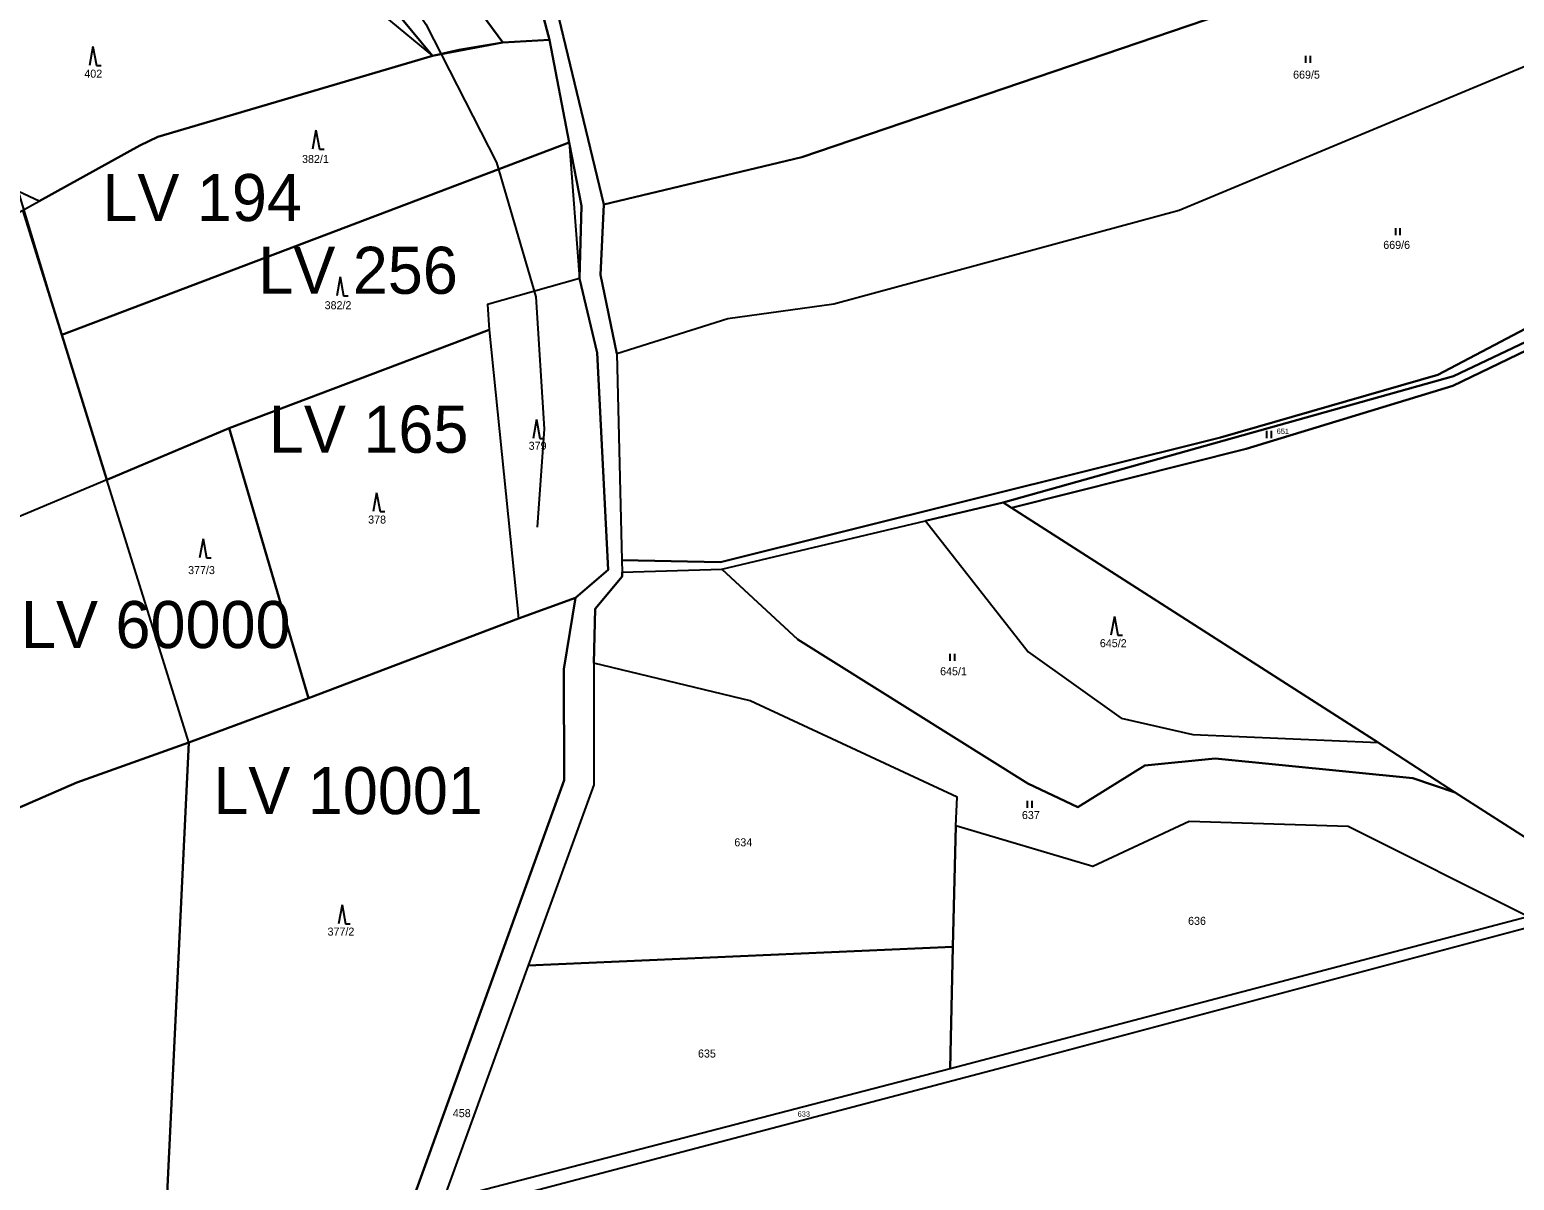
# Model space of a CAD drawing. Extents: x -590606 to -587796, y -1065936 to -1062515.
# Drawn here: x -590130 to -589814.6, y -1065080 to -1064835.5 of the extents above; entities that cross this region are included whole.
import ezdxf

# ---------------------------------------------------------------- set-up
doc = ezdxf.new("R2010")
doc.units = 0
for name, color, linetype in [('Lesy', 7, 'Continuous'), ('Parcela nároku', 7, 'Continuous'), ('Plocha pro ocenění', 7, 'Continuous'), ('Tok', 7, 'Continuous'), ('Vrstva 30', 7, 'Continuous'), ('Čísla LV', 7, 'Continuous')]:
    doc.layers.add(name, color=color, linetype=linetype)

msp = doc.modelspace()

# ---------------------------------------------------------------- linework, layer by layer
at = {"layer": 'Lesy'}
for p, q in [((-590123.19, -1064900.34), (-590015.37, -1064859.51)), ((-590096.21, -1064986.96), (-590070.76, -1064977.54))]:
    msp.add_line(p, q, dxfattribs=at)
for points in [[(-590044.4, -1064841.09), (-590029.51, -1064838.25), (-590019.58, -1064837.67)], [(-590131.43, -1064873.88), (-590127.95, -1064871.98), (-590106.62, -1064860.16), (-590102.75, -1064858.29), (-590044.4, -1064841.09)], [(-590113.59, -1064931.15), (-590087.61, -1064920.23), (-590032.41, -1064899.32)], [(-590087.61, -1064920.23), (-590070.76, -1064977.54), (-590026.19, -1064960.68), (-590014.04, -1064956.28)]]:
    msp.add_lwpolyline(points, dxfattribs=at)
at = {"layer": 'Parcela nároku'}
for points in [[(-590085.05, -1064746.07), (-590075.63, -1064745.31), (-590052.18, -1064731.26), (-590049.73, -1064728.85), (-590029.38, -1064789.34), (-590050.58, -1064809.55), (-590029.51, -1064838.25), (-590038.82, -1064839.84), (-590044.4, -1064841.09), (-590051.27, -1064832.84), (-590064.68, -1064824.28), (-590070.56, -1064805.35), (-590079.14, -1064802.65), (-590083.28, -1064800.94), (-590090.57, -1064795.95)], [(-589879.87, -1064753.99), (-589868.03, -1064748.13), (-589866.87, -1064751.2), (-589721.04, -1064765.62), (-589732.48, -1064773.33), (-589781.14, -1064797.6), (-589848.05, -1064822.46), (-589965.99, -1064862.62), (-590008.01, -1064872.65), (-590021.45, -1064817.05), (-590021.33, -1064814.7), (-589976.81, -1064797.92), (-589940.65, -1064780.54)], [(-590050.58, -1064809.55), (-590029.38, -1064789.34), (-590030.32, -1064781.93), (-590026.74, -1064766.14), (-590014.61, -1064753.36), (-589996.74, -1064775.17), (-590001.82, -1064781.5), (-590022.96, -1064799.52), (-590024.4, -1064815.82), (-590024.63, -1064818.7), (-590019.58, -1064837.67), (-590029.51, -1064838.25)], [(-589848.05, -1064822.46), (-589781.14, -1064797.6), (-589732.48, -1064773.33), (-589721.04, -1064765.62), (-589713.8, -1064760.35), (-589694.16, -1064785.11), (-589709.51, -1064796.54), (-589749.8, -1064818.94), (-589790.83, -1064834.34), (-589885.81, -1064873.92), (-589959.21, -1064893.84), (-589981.68, -1064896.99), (-590005.25, -1064904.42), (-590008.77, -1064887.64), (-590008.01, -1064872.65), (-589965.99, -1064862.62)], [(-589749.8, -1064818.94), (-589790.83, -1064834.34), (-589885.81, -1064873.92), (-589959.21, -1064893.84), (-589981.68, -1064896.99), (-590005.25, -1064904.42), (-590004.21, -1064948.26), (-589983.27, -1064948.69), (-589877.03, -1064922.22), (-589830.91, -1064908.85), (-589764.34, -1064873.79), (-589722.86, -1064853.73), (-589698.59, -1064837.06), (-589669.05, -1064824.3), (-589664.99, -1064821.89), (-589694.16, -1064785.11), (-589709.51, -1064796.54)], [(-590182.24, -1064846.33), (-590153.03, -1064819.2), (-590124.7, -1064831.07), (-590079.14, -1064802.65), (-590070.56, -1064805.35), (-590064.68, -1064824.28), (-590051.27, -1064832.84), (-590044.4, -1064841.09), (-590102.75, -1064858.29), (-590106.62, -1064860.16), (-590127.95, -1064871.98), (-590132.38, -1064869.89)], [(-589830.91, -1064908.85), (-589877.03, -1064922.22), (-589983.27, -1064948.69), (-590004.21, -1064948.26), (-590004.15, -1064950.82), (-589982.95, -1064950.18), (-589939.73, -1064939.92), (-589923.24, -1064936.02), (-589827.57, -1064909.16), (-589809.38, -1064900.48), (-589740.68, -1064866.6), (-589722.41, -1064857.38), (-589696.42, -1064842.01), (-589688.26, -1064837.19), (-589677.04, -1064831.33), (-589667.75, -1064826.48), (-589669.05, -1064824.3), (-589698.59, -1064837.06), (-589722.86, -1064853.73), (-589764.34, -1064873.79)], [(-590102.75, -1064858.29), (-590044.4, -1064841.09), (-590038.82, -1064839.84), (-590029.51, -1064838.25), (-590019.58, -1064837.67), (-590015.37, -1064859.51), (-590123.19, -1064900.34), (-590131.43, -1064873.88), (-590127.95, -1064871.98), (-590106.62, -1064860.16)], [(-590032.74, -1064893.95), (-590032.41, -1064899.32), (-590087.61, -1064920.23), (-590113.59, -1064931.15), (-590123.19, -1064900.34), (-590015.37, -1064859.51), (-590012.77, -1064872.97), (-590013.23, -1064888.37)], [(-590235.19, -1064919.07), (-590258.37, -1064938.81), (-590256.84, -1064941.98), (-590233.92, -1064922), (-590180.87, -1064901.24), (-590131.43, -1064873.88), (-590127.95, -1064871.98), (-590132.38, -1064869.89), (-590182.23, -1064898.16)], [(-590306.19, -1064982.83), (-590256.84, -1064941.98), (-590233.92, -1064922), (-590180.87, -1064901.24), (-590131.43, -1064873.88), (-590123.19, -1064900.34), (-590113.59, -1064931.15), (-590167.74, -1064953.92), (-590233.72, -1064986.21), (-590284.11, -1065022.42), (-590293.83, -1065027.95)], [(-590013.23, -1064888.37), (-590032.74, -1064893.95), (-590032.41, -1064899.32), (-590026.19, -1064960.68), (-590014.04, -1064956.28), (-590007.09, -1064950.34), (-590009.44, -1064904.18)], [(-590087.61, -1064920.23), (-590032.41, -1064899.32), (-590026.19, -1064960.68), (-590070.76, -1064977.54)], [(-589809.38, -1064900.48), (-589827.57, -1064909.16), (-589923.24, -1064936.02), (-589921.46, -1064937.16), (-589871.6, -1064924.56), (-589827.68, -1064911.18), (-589808.02, -1064901.71)], [(-589718.4, -1064982.65), (-589808.02, -1064901.71), (-589827.68, -1064911.18), (-589871.6, -1064924.56), (-589921.46, -1064937.16), (-589843.52, -1064987), (-589827.23, -1064997.59), (-589795.76, -1065017.7), (-589790.16, -1065012.34), (-589792.56, -1065010.99), (-589738.86, -1064988.82)], [(-590113.59, -1064931.15), (-590087.61, -1064920.23), (-590070.76, -1064977.54), (-590096.21, -1064986.96)], [(-590284.11, -1065022.42), (-590270.57, -1065073.39), (-590227.11, -1065047.54), (-590206.41, -1065035.68), (-590149.81, -1065008.44), (-590119.96, -1064995.5), (-590096.21, -1064986.96), (-590113.59, -1064931.15), (-590167.74, -1064953.92), (-590233.72, -1064986.21)], [(-589843.52, -1064987), (-589921.46, -1064937.16), (-589923.24, -1064936.02), (-589939.73, -1064939.92), (-589917.91, -1064967.76), (-589898.15, -1064981.84), (-589882.91, -1064985.28)], [(-589939.73, -1064939.92), (-589917.91, -1064967.76), (-589898.15, -1064981.84), (-589882.91, -1064985.28), (-589843.52, -1064987), (-589827.23, -1064997.59), (-589836.22, -1064994.59), (-589878.15, -1064990.41), (-589893.12, -1064991.88), (-589907.33, -1065000.76), (-589917.96, -1064995.7), (-589966.86, -1064965.11), (-589982.95, -1064950.18)], [(-589893.12, -1064991.88), (-589878.15, -1064990.41), (-589836.22, -1064994.59), (-589827.23, -1064997.59), (-589795.76, -1065017.7), (-589802.07, -1065023.73), (-589806.02, -1065022.39), (-589811.77, -1065023.97), (-589849.91, -1065004.87), (-589883.73, -1065003.75), (-589904.18, -1065013.33), (-589933.24, -1065004.69), (-589933.01, -1064998.63), (-589976.96, -1064978.12), (-590010.18, -1064970.13), (-590009.89, -1064958.56), (-590004.13, -1064951.75), (-590004.15, -1064950.82), (-589982.95, -1064950.18), (-589966.86, -1064965.11), (-589917.96, -1064995.7), (-589907.33, -1065000.76)], [(-590087.91, -1065095.23), (-590071.31, -1065090.46), (-590048.46, -1065083.71), (-590016.47, -1064995), (-590016.56, -1064971.44), (-590014.04, -1064956.28), (-590026.19, -1064960.68), (-590070.76, -1064977.54), (-590096.21, -1064986.96), (-590100.91, -1065085.81), (-590171.34, -1065136.57), (-590141.63, -1065124.76), (-590094.63, -1065099.49)], [(-589933.01, -1064998.63), (-589976.96, -1064978.12), (-590010.18, -1064970.13), (-590010.19, -1064996.02), (-590024.11, -1065034.41), (-589933.87, -1065030.44), (-589933.24, -1065004.69)], [(-590186.86, -1065144.42), (-590171.34, -1065136.57), (-590100.91, -1065085.81), (-590096.21, -1064986.96), (-590119.96, -1064995.5), (-590149.81, -1065008.44), (-590206.41, -1065035.68), (-590227.11, -1065047.54)], [(-589811.77, -1065023.97), (-589849.91, -1065004.87), (-589883.73, -1065003.75), (-589904.18, -1065013.33), (-589933.24, -1065004.69), (-589933.87, -1065030.44), (-589934.45, -1065056.25)], [(-589806.02, -1065022.39), (-589802.07, -1065023.73), (-589923.15, -1065056.06), (-590043.11, -1065087.66), (-590042.18, -1065084.25), (-589934.45, -1065056.25), (-589811.77, -1065023.97)], [(-589731.97, -1065078.6), (-589747.98, -1065071.62), (-589756.67, -1065059.05), (-589771, -1065049.48), (-589784.67, -1065037.04), (-589802.07, -1065023.73), (-589923.15, -1065056.06), (-590043.11, -1065087.66), (-590064.6, -1065165.95), (-590006.04, -1065151.63), (-589920.53, -1065125.45)], [(-590024.11, -1065034.41), (-590042.18, -1065084.25), (-589934.45, -1065056.25), (-589933.87, -1065030.44)]]:
    msp.add_lwpolyline(points, close=True, dxfattribs=at)
for points in [[(-590021.45, -1064817.05), (-590008.01, -1064872.65), (-590008.77, -1064887.64), (-590005.25, -1064904.42), (-590004.21, -1064948.26), (-590004.15, -1064950.82), (-590004.13, -1064951.75), (-590009.89, -1064958.56), (-590010.18, -1064970.13), (-590010.19, -1064996.02), (-590024.11, -1065034.41), (-590042.18, -1065084.25)], [(-590048.46, -1065083.71), (-590016.47, -1064995), (-590016.56, -1064971.44), (-590014.04, -1064956.28), (-590007.09, -1064950.34), (-590009.44, -1064904.18), (-590013.23, -1064888.37), (-590012.77, -1064872.97), (-590015.37, -1064859.51), (-590019.58, -1064837.67), (-590024.63, -1064818.7)]]:
    msp.add_lwpolyline(points, dxfattribs=at)
at = {"layer": 'Plocha pro ocenění'}
for points in [[(-590162.33, -1064773.04), (-590115.36, -1064781.23), (-590111.01, -1064781.85), (-590090.57, -1064795.95), (-590083.28, -1064800.94), (-590070.56, -1064805.35), (-590064.68, -1064824.28), (-590044.4, -1064841.09), (-590029.51, -1064838.25), (-590019.58, -1064837.67), (-590015.37, -1064859.51), (-590013.23, -1064888.37), (-590009.44, -1064904.18), (-590007.09, -1064950.34), (-590014.04, -1064956.28), (-590016.56, -1064971.44), (-590016.47, -1064995), (-590048.46, -1065083.71)], [(-590171.34, -1065136.57), (-590100.91, -1065085.81), (-590096.21, -1064986.96), (-590113.59, -1064931.15), (-590123.19, -1064900.34), (-590132.38, -1064869.89), (-590182.24, -1064846.33), (-590220.42, -1064866.89), (-590318.99, -1064904.37), (-590325.07, -1064907.04), (-590326.4, -1064871.7), (-590357.08, -1064885.44), (-590371.89, -1064892.14), (-590406.17, -1064909.87), (-590416.8, -1064913.27), (-590479.54, -1064933.75)]]:
    msp.add_lwpolyline(points, dxfattribs=at)
at = {"layer": 'Tok'}
msp.add_lwpolyline([(-590438.41, -1064819.57), (-590435.96, -1064818.69), (-590427.03, -1064816.54), (-590407.51, -1064812.59), (-590381.07, -1064804.84), (-590326.05, -1064786.37), (-590308.1, -1064778.43), (-590294.28, -1064774.37), (-590288.67, -1064773.61), (-590271.08, -1064781.17), (-590259.53, -1064781.6), (-590246.44, -1064780.74), (-590213.85, -1064774.68), (-590162.37, -1064761.96), (-590128.21, -1064763.66), (-590098.65, -1064772.87), (-590084.72, -1064783.05), (-590067.4, -1064801.95), (-590045.87, -1064834.39), (-590030.83, -1064863.75), (-590022.45, -1064892.28), (-590020.72, -1064920.32), (-590022.17, -1064941.23)], dxfattribs=at)
at = {"layer": 'Vrstva 30'}
for p, q in [((-590116.56, -1064839.12), (-590117.3, -1064843.12)), ((-590116.56, -1064839.12), (-590115.83, -1064843.12)), ((-590115.83, -1064843.12), (-590114.83, -1064843.12)), ((-589858.96, -1064841.09), (-589858.96, -1064842.59)), ((-589857.94, -1064842.59), (-589857.94, -1064841.09)), ((-590069.18, -1064856.9), (-590069.92, -1064860.9)), ((-590069.18, -1064856.9), (-590068.45, -1064860.9)), ((-590068.45, -1064860.9), (-590067.45, -1064860.9)), ((-589839.88, -1064877.72), (-589839.88, -1064879.22)), ((-589838.85, -1064879.22), (-589838.85, -1064877.72)), ((-590064.04, -1064888.07), (-590064.78, -1064892.07)), ((-590064.04, -1064888.07), (-590063.31, -1064892.07)), ((-590063.31, -1064892.07), (-590062.31, -1064892.07)), ((-590022.34, -1064918.37), (-590023.08, -1064922.37)), ((-590022.34, -1064918.37), (-590021.61, -1064922.37)), ((-589867.24, -1064920.8), (-589867.24, -1064922.3)), ((-589866.21, -1064922.3), (-589866.21, -1064920.8)), ((-590021.61, -1064922.37), (-590020.61, -1064922.37)), ((-590056.3, -1064933.92), (-590057.04, -1064937.92)), ((-590056.3, -1064933.92), (-590055.57, -1064937.92)), ((-590055.57, -1064937.92), (-590054.57, -1064937.92)), ((-590093.17, -1064943.75), (-590093.91, -1064947.75)), ((-590093.17, -1064943.75), (-590092.44, -1064947.75)), ((-590092.44, -1064947.75), (-590091.44, -1064947.75)), ((-589899.58, -1064960.19), (-589900.32, -1064964.19)), ((-589899.58, -1064960.19), (-589898.85, -1064964.19)), ((-589898.85, -1064964.19), (-589897.85, -1064964.19)), ((-589934.53, -1064968.17), (-589934.53, -1064969.67)), ((-589933.51, -1064969.67), (-589933.51, -1064968.17)), ((-589918.09, -1064999.39), (-589918.09, -1065000.89)), ((-589917.07, -1065000.89), (-589917.07, -1064999.39)), ((-590063.64, -1065021.49), (-590064.38, -1065025.49)), ((-590063.64, -1065021.49), (-590062.91, -1065025.49)), ((-590062.91, -1065025.49), (-590061.91, -1065025.49))]:
    msp.add_line(p, q, dxfattribs=at)

# ---------------------------------------------------------------- texts
at = {"layer": 'Parcela nároku'}
for s, height, p in [('402', 1.7, (-590118.38, -1064845.73)), ('669/5', 1.7, (-589861.62, -1064845.94)), ('382/1', 1.7, (-590072.14, -1064863.86)), ('669/6', 1.7, (-589842.47, -1064882.11)), ('382/2', 1.7, (-590067.34, -1064894.93)), ('651', 1.14, (-589865.11, -1064921.44)), ('379', 1.7, (-590024, -1064924.8)), ('378', 1.7, (-590058.09, -1064940.47)), ('377/3', 1.7, (-590096.34, -1064951.21)), ('645/2', 1.7, (-589902.67, -1064966.74)), ('645/1', 1.7, (-589936.6, -1064972.71)), ('637', 1.7, (-589919.23, -1065003.26)), ('634', 1.7, (-589980.31, -1065009.05)), ('377/2', 1.7, (-590066.72, -1065028.02)), ('636', 1.7, (-589883.93, -1065025.74)), ('635', 1.7, (-589988.03, -1065053.93)), ('458', 1.7, (-590040.11, -1065066.6)), ('633', 1.14, (-589966.87, -1065066.49))]:
    msp.add_text(s, height=height, dxfattribs=at).set_placement(p)
at = {"layer": 'Čísla LV'}
for s, p in [('LV 194', (-590114.55, -1064876.2)), ('LV 256', (-590081.43, -1064891.66)), ('LV 165', (-590079.18, -1064925.43)), ('LV 60000', (-590131.84, -1064966.93)), ('LV 10001', (-590090.98, -1065002.22))]:
    msp.add_text(s, height=10, dxfattribs=at).set_placement(p)

doc.saveas('drawing.dxf')
